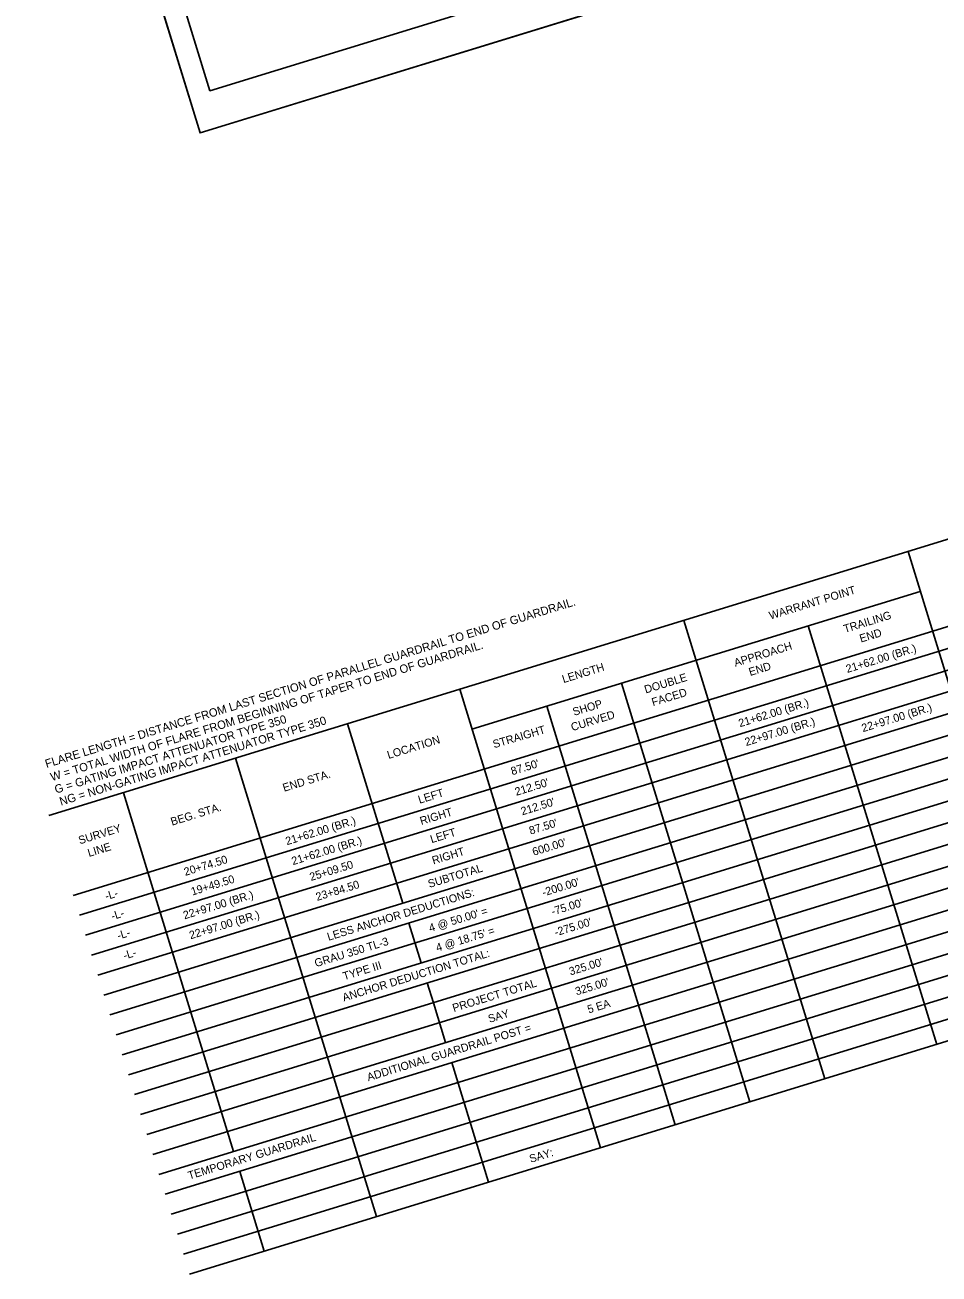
# Model space of a CAD drawing. Extents: x 2528815 to 2532488, y 739965 to 742287.
# Drawn here: x 2530077 to 2530625, y 739965 to 740714 of the extents above; entities that cross this region are included whole.
import ezdxf

# ---------------------------------------------------------------- set-up
doc = ezdxf.new("R2010")
doc.units = 0
for name, color, linetype in [('Sheet Cutting Line CELL', 7, 'Continuous'), ('Sheet Plot Border Inside CELL', 7, 'Continuous'), ('Sheet Plot Border Outside CELL', 7, 'Continuous'), ('Sheet Summary Combination CELL', 7, 'Continuous'), ('Sheet Summary Combination Grid CELL', 7, 'Continuous')]:
    doc.layers.add(name, color=color, linetype=linetype)

msp = doc.modelspace()

# ---------------------------------------------------------------- linework, layer by layer
at = {"layer": 'Sheet Cutting Line CELL'}
for p in [(2529858.69, 741700.56), (2531791.53, 741143.79)]:
    msp.add_line(p, (2530181.83, 740649.09), dxfattribs=at)
at = {"layer": 'Sheet Plot Border Inside CELL'}
msp.add_lwpolyline([(2531470.68, 742172.47), (2529877.71, 741682.92), (2530187.66, 740674.37), (2531780.63, 741163.93)], close=True, dxfattribs=at)
at = {"layer": 'Sheet Plot Border Outside CELL'}
msp.add_lwpolyline([(2531468.39, 742195.25), (2529858.69, 741700.56), (2530181.83, 740649.09), (2531791.53, 741143.79)], close=True, dxfattribs=at)
at = {"layer": 'Sheet Summary Combination Grid CELL'}
for p, q in [((2530091.06, 740239.79), (2531524.88, 740680.43)), ((2530105.75, 740191.99), (2531539.57, 740632.63)), ((2530109.42, 740180.04), (2531543.24, 740620.68)), ((2530113.1, 740168.1), (2531546.91, 740608.74)), ((2530116.77, 740156.15), (2531550.59, 740596.79)), ((2530120.44, 740144.2), (2531554.26, 740584.84)), ((2530124.11, 740132.25), (2531557.93, 740572.89)), ((2530127.78, 740120.3), (2531561.6, 740560.94)), ((2530131.46, 740108.35), (2531565.27, 740548.99)), ((2530135.13, 740096.4), (2531568.95, 740537.05)), ((2530138.8, 740084.46), (2531572.62, 740525.1)), ((2530142.47, 740072.51), (2531576.29, 740513.15)), ((2530146.14, 740060.56), (2531579.96, 740501.2)), ((2530149.82, 740048.61), (2531583.63, 740489.25)), ((2530153.49, 740036.66), (2531587.31, 740477.3)), ((2530157.16, 740024.71), (2531590.98, 740465.35)), ((2530160.83, 740012.76), (2531594.65, 740453.41)), ((2530164.5, 740000.82), (2531598.32, 740441.46)), ((2530168.18, 739988.87), (2531601.99, 740429.51)), ((2530171.85, 739976.92), (2531605.67, 740417.56)), ((2530175.52, 739964.97), (2531609.34, 740405.61)), ((2530606.33, 740398.14), (2530690.79, 740123.32)), ((2530344.83, 740291.62), (2530613.67, 740374.24)), ((2530471.93, 740356.84), (2530556.39, 740082.02)), ((2530546.48, 740353.59), (2530623.59, 740102.67)), ((2530434.45, 740319.16), (2530511.56, 740068.24)), ((2530337.49, 740315.52), (2530421.95, 740040.7)), ((2530389.66, 740305.4), (2530466.78, 740054.48)), ((2530270.29, 740294.87), (2530303.34, 740187.33)), ((2530203.09, 740274.21), (2530287.55, 739999.4)), ((2530135.85, 740253.55), (2530201.94, 740038.48)), ((2530307.01, 740175.38), (2530314.35, 740151.48)), ((2530318.03, 740139.54), (2530321.7, 740127.59)), ((2530321.7, 740127.59), (2530329.04, 740103.69)), ((2530332.71, 740091.74), (2530354.75, 740020.05)), ((2530205.61, 740026.53), (2530220.3, 739978.73))]:
    msp.add_line(p, q, dxfattribs=at)

# ---------------------------------------------------------------- texts
at = {"layer": 'Sheet Summary Combination CELL'}
for s, height, rotation, p in [('WARRANT POINT', 4.8, 17.08323, (2530523.84, 740357.3)), ('FLARE LENGTH = DISTANCE FROM LAST SECTION OF PARALLEL GUARDRAIL TO END OF GUARDRAIL.', 5.0001, 17.08323, (2530089.74, 740268.34)), ('TRAILING', 4.8, 17.08323, (2530568.5, 740349.32)), ('END', 4.8, 17.08323, (2530578.08, 740343.53)), ('W = TOTAL WIDTH OF FLARE FROM BEGINNING OF TAPER TO END OF GUARDRAIL.', 5.0001, 17.08323, (2530092.95, 740260.44)), ('APPROACH', 4.8, 17.08323, (2530502.81, 740329.03)), ('21+62.00 (BR.)', 4.8, 17.08323, (2530569.94, 740325.32)), ('LENGTH', 4.8, 17.08323, (2530399.75, 740319.22)), ('DOUBLE', 4.8, 17.08323, (2530449.06, 740312.98)), ('END', 4.8, 17.08323, (2530511.68, 740323.49)), ('FACED', 4.8, 17.08323, (2530453.43, 740305.38)), ('21+62.00 (BR.)', 4.8, 17.08323, (2530505.52, 740292.76)), ('CURVED', 4.8, 17.08323, (2530405.05, 740290.41)), ('SHOP', 4.8, 17.08323, (2530406.1, 740299.57)), ('22+97.00 (BR.)', 4.8, 17.08323, (2530579.36, 740289.83)), ('G = GATING IMPACT ATTENUATOR TYPE 350', 5.0001, 17.08323, (2530095.44, 740252.96)), ('NG = NON-GATING IMPACT ATTENUATOR TYPE 350', 5.0001, 17.08323, (2530098.38, 740245.75)), ('22+97.00 (BR.)', 4.8, 17.08323, (2530509.27, 740281.46)), ('LOCATION', 4.8, 17.08323, (2530294.83, 740273.74)), ('STRAIGHT', 4.8, 16.44737, (2530358.13, 740280.17)), ("87.50'", 4.8, 17.08323, (2530369.01, 740263.99)), ('END STA.', 4.8, 17.08323, (2530232.19, 740254.07)), ("212.50'", 4.8, 17.08323, (2530371.42, 740251.65)), ('LEFT', 4.8, 17.08323, (2530313.4, 740246.9)), ("212.50'", 4.8, 17.08323, (2530375.02, 740239.94)), ('BEG. STA.', 4.8, 17.08323, (2530165, 740233.74)), ('RIGHT', 4.8, 17.08323, (2530314.47, 740234.15)), ('SURVEY', 4.8, 17.08323, (2530109.7, 740222.55)), ('21+62.00 (BR.)', 4.8, 17.08323, (2530233.85, 740222.03)), ("87.50'", 4.8, 17.08323, (2530379.96, 740228.38)), ('21+62.00 (BR.)', 4.8, 17.08323, (2530237.52, 740210.08)), ('LEFT', 4.8, 17.08323, (2530320.67, 740223.24)), ('LINE', 4.8, 17.08323, (2530115.21, 740214.99)), ('RIGHT', 4.8, 17.08323, (2530321.74, 740210.49)), ("600.00'", 4.8, 17.08323, (2530381.88, 740215.65)), ('20+74.50', 4.8, 17.08323, (2530172.97, 740203.64)), ('25+09.50', 4.8, 17.08323, (2530248.33, 740200.59)), ('SUBTOTAL', 4.8, 17.08323, (2530319.32, 740196.43)), ('19+49.50', 4.8, 17.08323, (2530177.19, 740191.86)), ('23+84.50', 4.8, 17.08323, (2530252.01, 740188.64)), ("-200.00'", 4.8, 17.08323, (2530387.73, 740191.28)), ('-L-', 4.8, 17.08323, (2530125.58, 740189.07)), ('22+97.00 (BR.)', 4.8, 17.08323, (2530172.48, 740177.59)), ('LESS ANCHOR DEDUCTIONS:', 4.8, 17.08323, (2530258.85, 740164.75)), ("-75.00'", 4.8, 17.08323, (2530393.22, 740179.89)), ('-L-', 4.8, 17.08323, (2530129.25, 740177.12)), ('22+97.00 (BR.)', 4.8, 17.08323, (2530176.16, 740165.64)), ("4 @ 50.00' =", 4.8, 17.08323, (2530319.82, 740169.99)), ("-275.00'", 4.8, 17.08323, (2530395.07, 740167.38)), ('-L-', 4.8, 17.08323, (2530132.85, 740165.41)), ("4 @ 18.75' =", 4.8, 17.08323, (2530324.04, 740158.21)), ('GRAU 350 TL-3', 4.8, 17.08323, (2530251.27, 740148.92)), ('-L-', 4.8, 17.08323, (2530136.52, 740153.46)), ('TYPE III', 4.8, 17.08323, (2530268.24, 740141.06)), ('ANCHOR DEDUCTION TOTAL:', 4.8, 17.08323, (2530268, 740128.33)), ("325.00'", 4.8, 17.08323, (2530403.92, 740143.95)), ('PROJECT TOTAL', 4.8, 17.08323, (2530333.98, 740122.03)), ("325.00'", 4.8, 17.08323, (2530407.59, 740132)), ('SAY', 4.8, 17.08323, (2530355.38, 740115.53)), ('5 EA', 4.8, 17.08323, (2530414.93, 740121.18)), ('ADDITIONAL GUARDRAIL POST = ', 4.8, 17.08323, (2530282.73, 740080.55)), ('TEMPORARY GUARDRAIL', 4.8, 17.08323, (2530175.37, 740021.55)), ('SAY:', 4.8, 17.08323, (2530380.1, 740031.59))]:
    msp.add_text(s, height=height, rotation=rotation, dxfattribs=at).set_placement(p)

doc.saveas('drawing.dxf')
